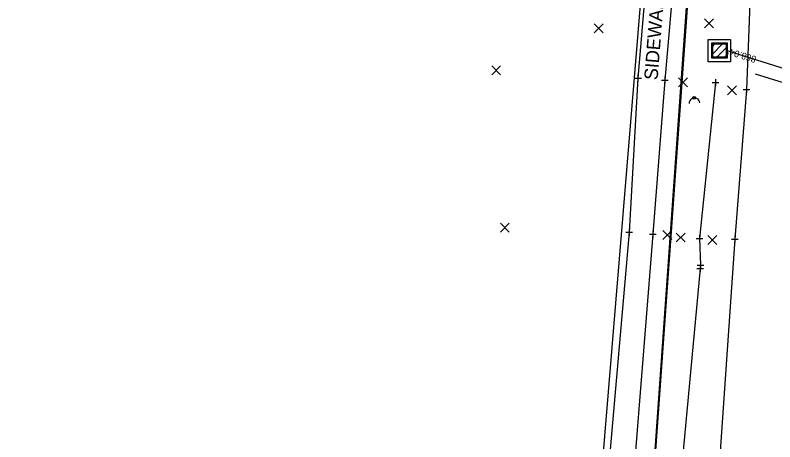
# Model space of a CAD drawing. Extents: x 1380550 to 1381945, y 468927 to 470496.
# Drawn here: x 1381495.3 to 1381608.3, y 470149.2 to 470212.8 of the extents above; entities that cross this region are included whole.
import ezdxf

# ---------------------------------------------------------------- set-up
doc = ezdxf.new("R2010")
doc.units = 0
for name, color, linetype in [('DR_X_Cells', 7, 'Continuous'), ('DR_X_Ditch', 7, 'Continuous'), ('DR_X_Storm_Sewer', 7, 'Continuous'), ('DR_X_Text', 7, 'Continuous'), ('GK_Drainage_Nodes', 7, 'Continuous'), ('PV_X_EOP', 7, 'Continuous'), ('PV_X_Walk', 7, 'Continuous'), ('RD_X_Text', 7, 'Continuous'), ('RW_X_Esmt_General', 7, 'Continuous'), ('SC_Scratch1', 7, 'Continuous'), ('SV_X_Random_Point', 7, 'Continuous'), ('SV_X_Shot_Marker', 7, 'Continuous'), ('UT_X_Electric', 7, 'Continuous'), ('UT_X_Misc_Cells', 7, 'Continuous'), ('UT_X_Telecom', 7, 'Continuous')]:
    doc.layers.add(name, color=color, linetype=linetype)

msp = doc.modelspace()

# ---------------------------------------------------------------- linework, layer by layer
at = {"layer": 'DR_X_Cells'}
for p, q in [((1381598.93, 470206.91), (1381600.69, 470208.67)), ((1381598.93, 470208.04), (1381599.56, 470208.67)), ((1381599.53, 470206.37), (1381601.22, 470208.07)), ((1381600.66, 470206.37), (1381601.22, 470206.94))]:
    msp.add_line(p, q, dxfattribs=at)
for points in [[(1381598.41, 470209.19), (1381601.74, 470209.19), (1381601.74, 470205.85), (1381598.41, 470205.85)], [(1381598.93, 470208.67), (1381601.22, 470208.67), (1381601.22, 470206.37), (1381598.93, 470206.37)], [(1381599.08, 470208.52), (1381601.08, 470208.52), (1381601.08, 470206.52), (1381599.08, 470206.52)]]:
    msp.add_lwpolyline(points, close=True, dxfattribs=at)
at = {"layer": 'DR_X_Ditch'}
msp.add_lwpolyline([(1381599.49, 470202.78), (1381597.12, 470179.51), (1381597.25, 470175.53), (1381597.2, 470175.03), (1381592.57, 470125.52), (1381589.1, 470072.43), (1381585.65, 470022.01), (1381581.71, 469971.4), (1381577.66, 469928.75), (1381573.1, 469880.44), (1381570.64, 469867.29)], dxfattribs=at)
at = {"layer": 'DR_X_Storm_Sewer'}
msp.add_line((1381632.9, 470197.56), (1381601.08, 470207.52), dxfattribs=at)
at = {"layer": 'DR_X_Text'}
msp.add_line((1381605.37, 470204.05), (1381623.58, 470198.35), dxfattribs=at)
at = {"layer": 'GK_Drainage_Nodes'}
for p, q in [((1381600.08, 470209.19), (1381600.08, 470209.19)), ((1381600.08, 470208.52), (1381600.08, 470208.52)), ((1381599.08, 470207.52), (1381599.08, 470207.52)), ((1381600.08, 470207.52), (1381600.08, 470207.52)), ((1381600.08, 470207.52), (1381600.08, 470207.52)), ((1381600.08, 470207.52), (1381600.08, 470207.52)), ((1381601.08, 470207.52), (1381601.08, 470207.52)), ((1381600.08, 470206.52), (1381600.08, 470206.52)), ((1381600.08, 470205.85), (1381600.08, 470205.85))]:
    msp.add_line(p, q, dxfattribs=at)
at = {"layer": 'PV_X_EOP'}
msp.add_lwpolyline([(1381575.39, 470244.04), (1381576.99, 470244.17), (1381579.54, 470245.54), (1381580.63, 470247.96), (1381580.96, 470249.54), (1381591.47, 470243.59), (1381595.25, 470241), (1381599.72, 470235.67), (1381603.29, 470229.19), (1381604.88, 470222.31), (1381604.1, 470201.73), (1381602.36, 470179.43), (1381598.63, 470125.51), (1381593.59, 470071.89), (1381589.53, 470020.65), (1381585.49, 469971.09), (1381582.04, 469928.84), (1381578.38, 469880.28), (1381576.86, 469862.02), (1381576.83, 469860.71), (1381576.16, 469857.38), (1381571.59, 469847.12), (1381563.14, 469838.25)], dxfattribs=at)
at = {"layer": 'PV_X_Walk'}
for points in [[(1381595.25, 470241), (1381595.01, 470239.38), (1381594.79, 470235.56), (1381591.94, 470203.13), (1381590.15, 470180.15), (1381585.84, 470126.11), (1381581.45, 470072.84), (1381577.22, 470021.47), (1381573.16, 469971.68), (1381569.7, 469929.43), (1381565.6, 469880.89), (1381564.41, 469867), (1381562.95, 469848.39), (1381561.9, 469840.88)], [(1381542.56, 470237.64), (1381568.34, 470236.69), (1381578.51, 470236.26), (1381584.49, 470236.02), (1381590.64, 470235.62), (1381587.95, 470203.42), (1381586.62, 470180.46), (1381581.93, 470126.46), (1381577.65, 470073.24), (1381573.2, 470021.54), (1381569.15, 469971.74), (1381565.64, 469929.65), (1381561.64, 469881.16), (1381560.46, 469867.32), (1381559.27, 469848.71), (1381558.35, 469840.14)]]:
    msp.add_lwpolyline(points, dxfattribs=at)
at = {"layer": 'RW_X_Esmt_General'}
msp.add_lwpolyline([(1381490.4, 469029.46), (1381590.2, 470237.18), (1380558.69, 470277.03)], dxfattribs=at)
at = {"layer": 'SV_X_Random_Point'}
for p, q in [((1381597.87, 470210.91), (1381599.21, 470212.25)), ((1381597.87, 470212.25), (1381599.21, 470210.91)), ((1381581.42, 470210.17), (1381582.75, 470211.51)), ((1381581.42, 470211.51), (1381582.75, 470210.17)), ((1381566.18, 470203.9), (1381567.51, 470205.24)), ((1381566.18, 470205.24), (1381567.51, 470203.9)), ((1381593.97, 470202.11), (1381595.31, 470203.45)), ((1381593.97, 470203.45), (1381595.31, 470202.11)), ((1381601.27, 470200.95), (1381602.61, 470202.28)), ((1381601.27, 470202.28), (1381602.61, 470200.95)), ((1381567.47, 470180.47), (1381568.8, 470181.81)), ((1381567.47, 470181.81), (1381568.8, 470180.47)), ((1381591.67, 470179.39), (1381593.01, 470180.72)), ((1381591.67, 470180.72), (1381593.01, 470179.39)), ((1381593.64, 470179), (1381594.98, 470180.33)), ((1381593.64, 470180.33), (1381594.98, 470179)), ((1381598.36, 470178.61), (1381599.69, 470179.94)), ((1381598.36, 470179.94), (1381599.69, 470178.61))]:
    msp.add_line(p, q, dxfattribs=at)
at = {"layer": 'SV_X_Shot_Marker'}
for p, q in [((1381587.95, 470203.92), (1381587.95, 470202.92)), ((1381587.45, 470203.42), (1381588.45, 470203.42)), ((1381587.95, 470203.42), (1381587.95, 470203.42)), ((1381591.44, 470203.13), (1381592.44, 470203.13)), ((1381591.94, 470203.63), (1381591.94, 470202.63)), ((1381591.94, 470203.13), (1381591.94, 470203.13)), ((1381598.99, 470202.78), (1381599.99, 470202.78)), ((1381599.49, 470203.28), (1381599.49, 470202.28)), ((1381599.49, 470202.78), (1381599.49, 470202.78)), ((1381603.6, 470201.73), (1381604.6, 470201.73)), ((1381604.1, 470202.23), (1381604.1, 470201.23)), ((1381604.1, 470201.73), (1381604.1, 470201.73)), ((1381586.12, 470180.46), (1381587.12, 470180.46)), ((1381586.62, 470180.96), (1381586.62, 470179.96)), ((1381586.62, 470180.46), (1381586.62, 470180.46)), ((1381589.65, 470180.15), (1381590.65, 470180.15)), ((1381590.15, 470180.65), (1381590.15, 470179.65)), ((1381590.15, 470180.15), (1381590.15, 470180.15)), ((1381596.62, 470179.51), (1381597.62, 470179.51)), ((1381597.12, 470180.01), (1381597.12, 470179.01)), ((1381597.12, 470179.51), (1381597.12, 470179.51)), ((1381601.86, 470179.43), (1381602.86, 470179.43)), ((1381602.36, 470179.93), (1381602.36, 470178.93)), ((1381602.36, 470179.43), (1381602.36, 470179.43)), ((1381596.75, 470175.53), (1381597.75, 470175.53)), ((1381597.2, 470175.53), (1381597.2, 470174.53)), ((1381597.25, 470176.03), (1381597.25, 470175.03)), ((1381597.25, 470175.53), (1381597.25, 470175.53)), ((1381596.7, 470175.03), (1381597.7, 470175.03)), ((1381597.2, 470175.03), (1381597.2, 470175.03))]:
    msp.add_line(p, q, dxfattribs=at)
at = {"layer": 'UT_X_Electric'}
msp.add_lwpolyline([(1381665.56, 470247.4), (1381595.79, 470220.83), (1381581.26, 470018.2), (1381571.97, 469887.64), (1381559.77, 469757.41), (1381543.86, 469565.78), (1381529.17, 469390.12), (1381515.28, 469203.1), (1381540.8, 469054.26)], dxfattribs=at)
at = {"layer": 'UT_X_Misc_Cells'}
msp.add_circle((1381596.31, 470200.47), 0.2, dxfattribs=at)
msp.add_arc((1381596.36, 470199.67), 0.8, 3.2449, 183.2449, dxfattribs=at)
at = {"layer": 'UT_X_Telecom'}
msp.add_lwpolyline([(1381665.56, 470247.4), (1381595.35, 470217.51), (1381581.26, 470018.2), (1381571.97, 469887.64), (1381559.77, 469757.41), (1381543.86, 469565.78), (1381529.17, 469390.12), (1381515.28, 469203.1), (1381540.8, 469054.26)], dxfattribs=at)

# ---------------------------------------------------------------- texts
at = {"layer": 'RD_X_Text'}
msp.add_text('SIDEWALK', height=2, rotation=85.521, dxfattribs=at).set_placement((1381590.86, 470203.07))
at = {"layer": 'SC_Scratch1'}
msp.add_text("868.04'", height=1, rotation=162.6187, dxfattribs=at).set_placement((1381605.65, 470206.61))

doc.saveas('drawing.dxf')
